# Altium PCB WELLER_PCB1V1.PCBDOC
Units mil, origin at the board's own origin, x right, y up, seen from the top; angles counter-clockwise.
Board outline 6000 x 4000 mil, 2 copper layers (Top Layer, Bottom Layer); 44 components, 40 nets, 155 pads, 1 vias.
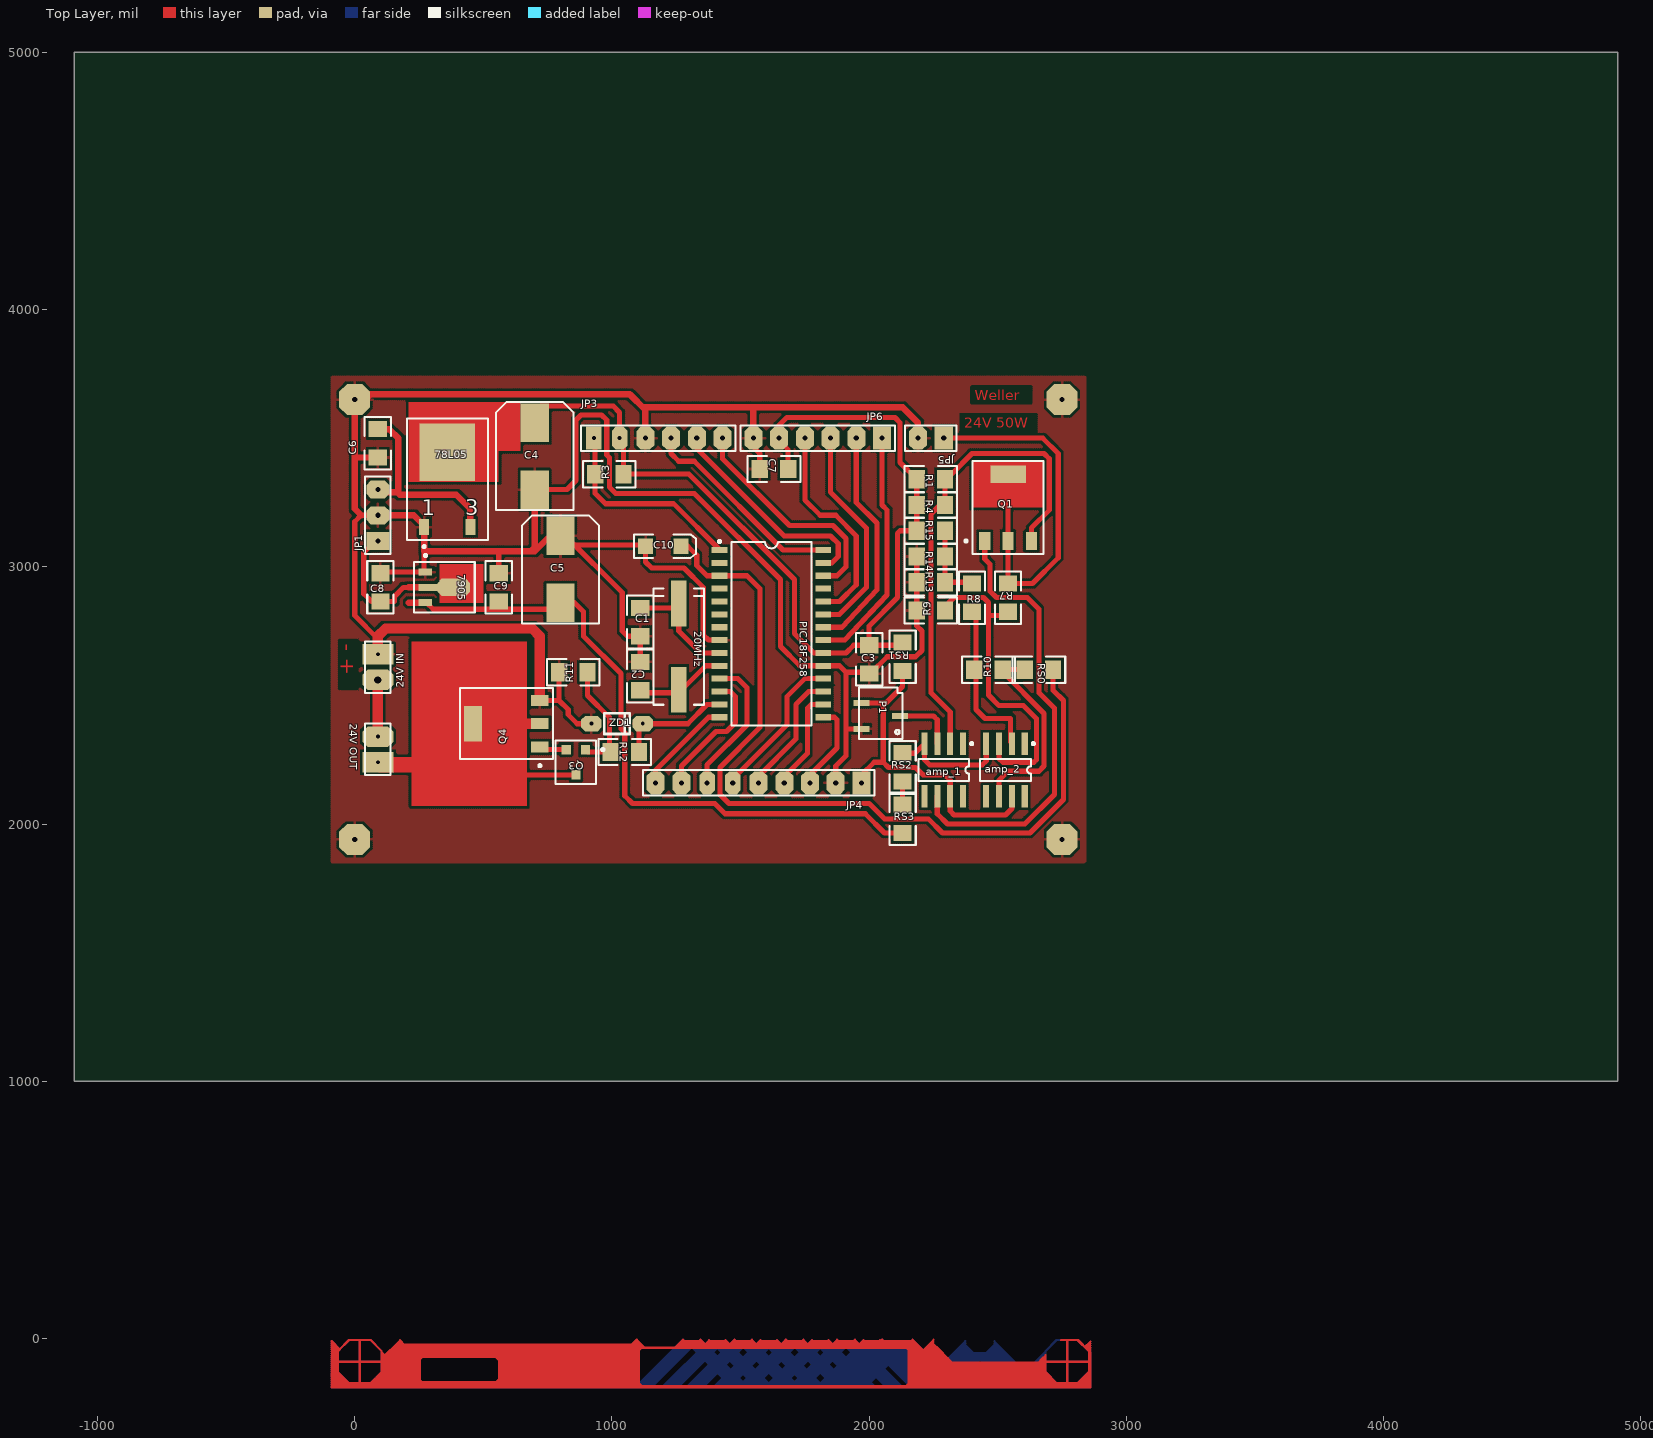
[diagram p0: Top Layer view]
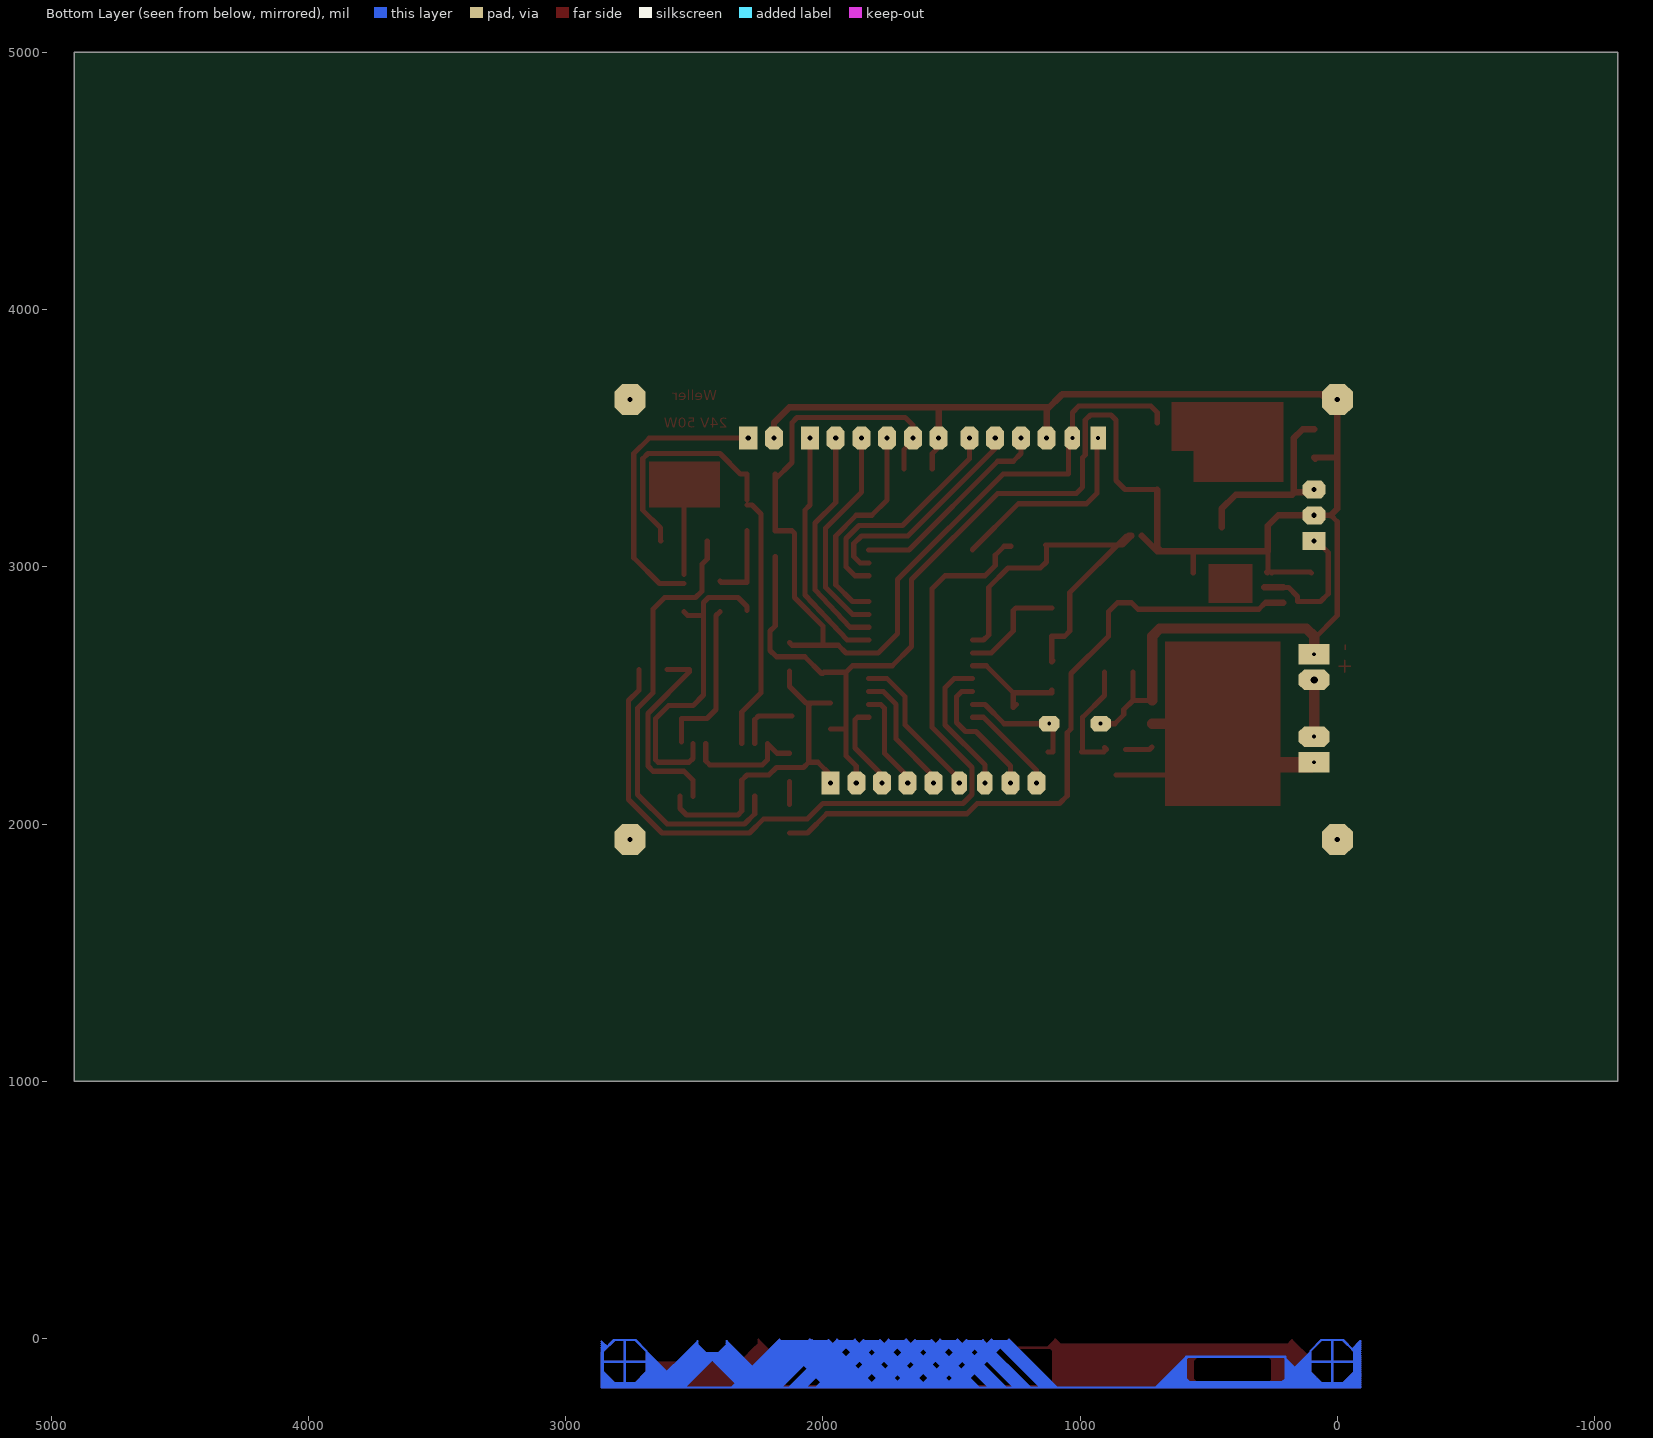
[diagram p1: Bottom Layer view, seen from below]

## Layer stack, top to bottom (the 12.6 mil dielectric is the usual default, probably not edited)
Top Layer: signal copper 1.4
Dielectric: dielectric 12.6, FR-4, Dk 4.8
Bottom Layer: signal copper 1.4

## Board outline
-1090,1000 -1090,5000 4910,5000 4910,1000

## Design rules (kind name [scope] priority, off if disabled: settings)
Clearance [All] p1: gap=10
ComponentClearance [All] p1 off: gap=10 collisioncheckmode=0
FanoutControl Fanout_BGA [IsBGA] p1 off: bgadir=Out bgaviamode=Centered fanoutstyle=Auto fanoutdirection=Alternating viagrid=1 // Fanout_BGA (Default Rule)
FanoutControl Fanout_LCC [IsLCC] p2 off: bgadir=Out bgaviamode=Centered fanoutstyle=Auto fanoutdirection=Alternating viagrid=1 // Fanout_LCC (Default Rule)
FanoutControl Fanout_SOIC [IsSOIC] p3 off: bgadir=Out bgaviamode=Centered fanoutstyle=Auto fanoutdirection=Alternating viagrid=1 // Fanout_SOIC (Default Rule)
FanoutControl Fanout_Small [(CompPinCount < 5)] p4 off: bgadir=Out bgaviamode=Centered fanoutstyle=Auto fanoutdirection=OutThenIn viagrid=1 // Fanout_Small (Default Rule)
FanoutControl Fanout_Default [All] p5 off: bgadir=Out bgaviamode=Centered fanoutstyle=Auto fanoutdirection=Alternating viagrid=1 // Fanout_Default (Default Rule)
Height [All] p1 off: minheight=0 maxheight=1000 prefheight=500
HoleSize [All] p1 off: absolutevalues=TRUE maxlimit=100 minlimit=1 maxpercent=80.000 minpercent=20.000
LayerPairs [All] p1 off: enforce=TRUE
PasteMaskExpansion [All] p1 off: expansion=0
PolygonConnect [All] p1: connectstyle=Relief reliefconductorwidth=10 reliefentries=4 polygonreliefangle="90 Angle"
RoutingCorners [All] p1 off: cornerstyle=45-Degree minsetback=100 maxsetback=100
RoutingLayers [All] p1 off: top layer=Horizontal bottom layer=Vertical
RoutingPriority [All] p1 off: routingpriority=0
RoutingTopology [All] p1 off: topology=Shortest
RoutingVias [All] p1: holewidth=28 width=50 viastyle="Through Hole" minholewidth=28 minwidth=50 maxholewidth=28 maxwidth=50
SolderMaskExpansion [All] p1 off: expansion=4
TestPointUsage [All] p1 off: valid=0 allowmultiple=FALSE
Testpoint [All] p1 off: side=15 testpointundercomponent=TRUE minsize=40 maxsize=100 preferedsize=60 minholesize=0 maxholesize=40 preferedholesize=32 testpointgrid=1 style=1023 order=1234567890
Width [All] p1: maxlimit=70 minlimit=10 preferedwidth=40 toplayer_prefwidth=20 bottomlayer_prefwidth=60 minimp=50.000000 maximp=50.000000 favimp=50.000000
4 further rules are at their usual default settings.

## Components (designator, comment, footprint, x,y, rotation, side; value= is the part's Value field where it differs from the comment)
20MHz "ECS-110-S-5P" BCY-F2/Z13 1260,2690 r270 top
"24V IN" "Header 2" HDR1X2#1 90,2660 r270 top
"24V OUT" "Header 2" HDR1X2#1 90,2240 r90 top
78L05 "MC33269DT-5.0" SIP-G3/Z11.05 360,3300 r0 top
7905 "79L05" SOT89/P1.5 330,2920 r270 top
amp_1 "TL071CD" SO-G8 2290,2210 r180 top
amp_2 "TL071CD" SO-G8 2530,2210 r180 top
C1 "Cap Semi" C3216-1206 1110,2785.12 r90 top
C2 "Cap Semi" C3216-1206 1110,2575.12 r270 top
C3 "Cap Semi" C3216-1206 2000,2640 r90 top
C4 "Cap Pol3" DSO-C3/X3.4 270,3880 r0 top
C5 "Cap Semi" DSO-C3/X3.4 370,3440 r0 top
C6 "Cap Semi" C3216-1206 90,3480 r90 top
C7 "Cap Semi" C3216-1206 1630,3380 r0 top (schematic designator C6)
C8 "Cap Semi" C3216-1206 100,2920 r90 top (schematic designator C7)
C9 "Cap Semi" C3216-1206 560,2920 r90 top (schematic designator C8)
C10 "Cap Pol3" DSO-F2/D6.1 1200,3080 r0 top
JP1 "Header 3" HDR1X3 90,3100 r90 top
JP3 "Header 6" HDR1X6#1 930,3500 r0 top
JP4 "Header 9" HDR1X9 1970,2160 r180 top
JP5 "Header 2" HDR1X2#2 2290,3500 r180 top
JP6 "Header 6" HDR1X6#2 2050,3500 r180 top
P1 "SMD POTI" "SMD poti" 2030,2420 r270 top
PIC18F258 "" SOIC28 1610,2740 r270 top
Q1 "BCP53T1" DSO-G3/C6.6 2540,3230 r0 top
Q3 "BC817" SOT23 860,2240 r180 top
Q4 "BCP56T1" DSO-G3/C6.6 590,2390 r90 top (schematic designator BDP949)
R1 "Res2" C3216-1206 2240,3340 r180 top
R3 "Res2" C3216-1206 990,3360 r0 top
R4 "Res2" C3216-1206 2240,3240 r180 top
R7 "Res2" C3216-1206 2540,2880 r270 top
R8 "Res2" C3216-1206 2400,2880 r270 top
R9 "Res2" C3216-1206 2240,2830 r0 top
R10 "Res2" C3216-1206 2463.88,2600 r0 top
R11 "Res2" C3216-1206 850,2590 r0 top
R12 "Res2" C3216-1206 1050,2280 r180 top
R13 "Res2" C3216-1206 2240,2940 r0 top
R14 "Res2" C3216-1206 2240,3040 r0 top
R15 "Res2" C3216-1206 2240,3140 r180 top
RS0 "Res2" C3216-1206 2660,2600 r0 top
RS1 "Res2" C3216-1206 2130,2650 r270 top
RS2 "Res2" C3216-1206 2130,2220 r270 top
RS3 "Res2" C3216-1206 2130,2020 r270 top
ZD1 "ZENER" Dioda200 920,2390 r0 top

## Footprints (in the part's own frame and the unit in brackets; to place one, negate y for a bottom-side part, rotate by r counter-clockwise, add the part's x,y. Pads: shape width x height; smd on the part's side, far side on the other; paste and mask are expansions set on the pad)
BCY-F2/Z13 [mm]
  rect 4.5x1.5 smd: 1(-4.25,0) 2(4.25,0)
  silkscreen extent -5.75,-2.5 5.75,2.5
C3216-1206 [mm]
  rect 1.6x1.8 smd: 1(-1.4,0) 2(1.4,0)
  silkscreen extent -2.6,-1.3 2.6,1.3
Dioda200 [mil]
  oct 80x60 hole 15: 1(0,0) 2(200,0)
  silkscreen extent 50,-40 150,40
DSO-C3/X3.4 [mil]
  rect 110x150 smd: 1(430,-320) 2(430,-580)
  silkscreen extent 280,-660 580,-240
DSO-F2/D6.1 [mm]
  rect 1.5x1.5 smd: 1(-1.75,0) 2(1.75,0)
  silkscreen extent -2.9,-1.15 3.2,1.15
DSO-G3/C6.6 [mm]
  rect 1.1x1.75 smd: 1(-2.3,-3.3) 2(0,-3.3) 3(2.3,-3.3)
  rect 3.5x1.75 smd: 4(0,3.3)
  silkscreen extent -4.27,-4.6 3.5,4.6
HDR1X2#1 [mil]
  rect 80x120 hole 15: 1(0,0)
  oct 80x120 hole 15: 2(100,0)
  silkscreen extent -50,-50 150,50
HDR1X2#2 [mil]
  rect 70x90 hole 20: 1(0,0)
  oct 70x90 hole 20: 2(100,0)
  silkscreen extent -50,-50 150,50
HDR1X3 [mil]
  rect 70x90 hole 20: 1(0,0)
  oct 70x90 hole 20: 2(100,0) 3(200,0)
  silkscreen extent -50,-50 250,50
HDR1X6#1 [mil]
  rect 60x90 hole 15: 1(0,0)
  oct 60x90 hole 15: 2(100,0)
  oct 70x90 hole 20: 3(200,0) 4(300,0) 5(400,0) 6(500,0)
  silkscreen extent -50,-50 550,50
HDR1X6#2 [mil]
  rect 70x90 hole 20: 1(0,0)
  oct 70x90 hole 20: 2(100,0) 3(200,0) 4(300,0) 5(400,0) 6(500,0)
  silkscreen extent -50,-50 550,50
HDR1X9 [mil]
  rect 70x90 hole 20: 1(0,0)
  oct 70x90 hole 20: 2(100,0) 3(200,0) 4(300,0) 5(400,0) 8(700,0) 9(800,0)
  oct 60x90 hole 20: 6(500,0) 7(600,0)
  silkscreen extent -50,-50 850,50
SIP-G3/Z11.05 [mm]
  rect 1x1.6 smd: 1(-2.285,-3.7) 3(2.285,-3.7)
  rect 5.5x5.7 smd: 4(0,3.7)
  silkscreen extent -4,-5.75 4,7.03
"SMD poti" [mm]
  rect 0.6x1.55 smd: 1(-1.27,-1.524) 2(0,2.286) 3(1.27,-1.524)
  silkscreen extent -2.79,-1.78 2.29,2.54
SO-G8 [mm]
  rect 0.6x2.2 smd: 1(-1.905,-2.6) 2(-0.635,-2.6) 3(0.635,-2.6) 4(1.905,-2.6) 5(1.905,2.6) 6(0.635,2.6) 7(-0.635,2.6) 8(-1.905,2.6)
  silkscreen extent -2.88,-2.72 2.5,1.1
SOIC28 [mm]
  rect 0.6x1.55 smd: 1(-8.255,-4.871) 2(-6.985,-4.871) 3(-5.715,-4.871) 4(-4.445,-4.871) 5(-3.175,-4.871) 6(-1.905,-4.871) 7(-0.635,-4.871) 8(0.635,-4.871) 9(1.905,-4.871) 10(3.175,-4.871) 11(4.445,-4.871) 12(5.715,-4.871) 13(6.985,-4.871) 14(8.255,-4.871) 15(8.255,5.379) 16(6.985,5.379) 17(5.715,5.379) 18(4.445,5.379) 19(3.175,5.379) 20(1.905,5.379) 21(0.635,5.379) 22(-0.635,5.379) 23(-1.905,5.379) 24(-3.175,5.379) 25(-4.445,5.379) 26(-5.715,5.379) 27(-6.985,5.379) 28(-8.255,5.379)
  silkscreen extent -9.23,-5 9.05,4.2
SOT23 [mm]
  rect 0.9x0.95 smd: B(-0.95,-1.25) C(0,1.25) E(0.95,-1.25)
  silkscreen extent -2.78,-2.15 2,2.15
SOT89/P1.5 [mm]
  oct 1.75x3.25 smd: 0(0,1.4)
  rect 0.7x1.35 smd: 1(-1.5,-1.4) 3(1.5,-1.4)
  rect 0.7x1.85 smd: 2(0,-1.15)
  silkscreen extent -3.27,-2.52 2.5,3.47

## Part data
20MHz: "Crystal Oscillator"
"24V IN" "24V OUT" JP5: "Header, 2-Pin"
78L05: "Low Dropout Positive Fixed Voltage Regulator"
amp_1 amp_2: "Low-Noise J-FET Single Operational Amplifier"
C1 C2 C3 C5 C6 C7 C8 C9: "Capacitor (Semiconductor SIM Model)"
C4 C10: "Polarized Capacitor (Surface Mount)"
JP1: "Header, 3-Pin"
JP3 JP6: "Header, 6-Pin"
JP4: "Header, 9-Pin"
P1: library part RPot1, "Potentiometer"
PIC18F258: library part PIC18F258
Q1: "PNP Silicon Epitaxial Transistor"
Q4: "NPN Silicon Epitaxial Transistor"
R1 R3 R4 R7 R8 R9 R10 R11 R12 R13 R14 R15 RS0 RS1 RS2 RS3: "Resistor"

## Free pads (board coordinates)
  oct 120x120 hole 20: 3(0,3650) 4(2750,3650) 5(0,1940) 6(2750,1940)

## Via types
v1: diameter 50, hole 28, Top Layer to Bottom Layer, 1 vias

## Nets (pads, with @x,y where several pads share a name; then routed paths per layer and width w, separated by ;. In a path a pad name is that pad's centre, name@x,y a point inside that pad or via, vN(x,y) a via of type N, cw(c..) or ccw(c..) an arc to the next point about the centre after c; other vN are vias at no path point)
GND: 78L05.1 7905.1 "24V IN.1" C1.1 C2.1 C3.1 C4.2 C5.1 C6.1 C7.1 C8.2 C9.2 C10.1 JP1.2 JP3.3 JP4.2 JP5.2 JP6.6 P1.3 pad.3 pad.4 pad.5 pad.6 PIC18F258.8 PIC18F258.19 Q4.3 R9.1 R11.1 R13.1 R14.1 ZD1.1 | length 11588.4
  Top Layer w20: 90,2720 0,2810 0,3175 25,3200 JP1.2 ; C8.2 103.94,2979.05 7905.1 ; 7905.1@255.12,2975.12 7905.1@259.05,2979.05 ; 270,3060 270,2983.94 7905.1 ; 7905.1@270.95,2975.12 7905.1 ; C9.2 560,3060 ; C4.2 825,3300 860,3335 860,3570 880,3590 960,3590 980,3570 980,3435 990,3425 990,3310 1015,3285 1320,3285 1655,2950 1655,2690 1730,2615 1885,2615 1910,2590 ; Q4.3 794.45,2480.55 ; R11.1 794.88,2480.98 794.45,2480.55 ; ZD1.1 865,2390 830,2425 830,2445 794.45,2480.55 ; C2.1@1105.12,2635.12 C2.1 C1.1 1060,2730 1040,2750 1040,2900 820,3120 C5.1 835,3085 C10.1@1135,3085 ; JP3.3 JP3.3@1130,3540 ; C10.1 1131.1,3018.9 1155,2995 1280,2995 1355,2920 1355,2735 1375,2715 PIC18F258.8 ; JP6.6 1550,3465 1574.88,3440.12 C7.1 ; JP4.2 1870,2225 1910,2265 1910,2590 ; 1910,2370 P1.3 ; R14.1 2184.88,2770.12 2205,2750 2205,2675 2180,2650 2070,2650 2004.88,2584.88 C3.1 1994.88,2590 1910,2590
  Top Layer w25: 0.12,3424.88 C6.1 C6.1@85.12,3420 ; 25,3200 0,3225 0,3610 60,3670 1070,3670 1130,3610 JP3.3 ; JP1.2 230,3200 78L05.1@270.01,3159.99 ; 78L05.1 270.01,3060.01 700,3060 C5.1@760,3120 ; 685,3060 700,3075 C4.2 ; C5.1 C5.1@810,3120 ; 1120,3620 2130,3620 2190,3560 JP5.2 ; JP6.6 1550,3620
  Top Layer w40: 90,2660 90,2730 120,2760 690,2760 719.92,2730.08 Q4.3
Net20MHz_1: 20MHz.1 C1.2 PIC18F258.9 | length 427.7
  Top Layer w20: C1.2 1249.76,2840.24 1260,2830 1260,2750 1345,2665 PIC18F258.9
Net20MHz_2: 20MHz.2 C2.2 PIC18F258.10 | length 436.3
  Top Layer w20: C2.2 1110,2510 20MHz.2@1260,2510 ; 20MHz.2@1247.8,2464.88 1260,2452.68 20MHz.2@1260,2510 ; PIC18F258.10 1365,2615 20MHz.2@1260,2510
"Net24V IN_2": "24V IN.2" "24V OUT.2" | length 220
  Top Layer w40: 90,2340 v1(90,2560)
"Net24V OUT_1": "24V OUT.1" Q3.C Q4.2 Q4.4 | length 865.2
  Top Layer w20: 635,2190 635.79,2190.79 Q3.C
  Top Layer w40: Q4.4 Q4.2
  Top Layer w60: 100,2230 480,2230
Net78L05_3: 78L05.3 C6.2 JP1.3 | length 771.3
  Top Layer w25: JP1.3 100,3290 170,3290 170,3500 134.88,3535.12 C6.2 ; 165,3290 175,3280 395,3280 449.96,3225.04 78L05.3
Net7905_2: 7905.0 7905.2 C8.1 JP1.1 | length 530.5
  Top Layer w20: JP1.1 80,3100 35,3055 35,2894.88 65,2864.88 154.88,2864.88 154.88,2884.88 190,2920 210,2920
  Top Layer w25: 210,2920 7905.2
NetC10_2: C10.2 PIC18F258.3 RS0.2 | length 3234.7
  Top Layer w20: C10.2 1295,3080 1330,3045 1330,3005 1370,2965 1525,2965 1575,2915 1575,2375 1420,2220 1420,2115 1455,2080 2000,2080 2060,2020 2230,2020 2285,1965 2625,1965 2755,2095 2755,2480 2715.12,2519.88 RS0.2 ; PIC18F258.3@1418.11,2965.12 PIC18F258.3
NetJP3_1: JP3.1 PIC18F258.1 R3.1 | length 792.5
  Top Layer w20: JP3.1 934.88,3495.12 934.88,3285 974.88,3245 1240,3245 1418.23,3066.77 PIC18F258.1
NetJP3_4: JP3.4 PIC18F258.28 | length 807.1
  Top Layer w20: JP3.4 1230,3440 1260,3410 1320,3410 1665,3065 PIC18F258.28
NetJP3_5: JP3.5 PIC18F258.27 | length 861.8
  Top Layer w20: JP3.5 1330,3460 1670,3120 1850,3120 1880,3090 1880,3040 1855,3015 PIC18F258.27
NetJP3_6: JP3.6 PIC18F258.26 | length 901.1
  Top Layer w20: JP3.6 1430,3420 1690,3160 1860,3160 1910,3110 1910,3000 1875,2965 PIC18F258.26
NetJP4_1: amp_1.7 amp_2.7 JP4.1 P1.1 RS1.2 | length 1329.9
  Top Layer w20: JP4.1 1970,2190 2020,2240 2055,2240 ; P1.1 2065,2470 2130,2535 RS1.2 ; 2045,2470 2055,2460 2055,2240 ; amp_2.7 2555,2060 2530,2035 2330,2035 2315,2050 2315,2170 2295,2190 2210,2190 2180,2220 2075,2220 2055,2240
NetJP4_3: JP4.3 PIC18F258.15 | length 345.9
  Top Layer w20: JP4.3 1770,2190 1875,2295 1875,2405 1865,2415 PIC18F258.15
NetJP4_4: JP4.4 PIC18F258.16 | length 395.3
  Top Layer w20: JP4.4 1670,2185 1760,2275 1760,2450 1775,2465 PIC18F258.16
NetJP4_5: JP4.5 PIC18F258.17 | length 492.5
  Top Layer w20: JP4.5 1570,2185 1715,2330 1715,2465 1765,2515 PIC18F258.17
NetJP4_6: JP4.6 PIC18F258.18 | length 592.8
  Top Layer w20: JP4.6 1470,2175 1680,2385 1680,2495 1750,2565 PIC18F258.18
NetJP4_7: JP4.7 PIC18F258.11 | length 555.5
  Top Layer w20: JP4.7 1370,2230 1525,2385 1525,2530 1490,2565 PIC18F258.11
NetJP4_8: JP4.8 PIC18F258.12 | length 515.5
  Top Layer w20: JP4.8 1270,2225 1405,2360 1445,2360 1480,2395 1480,2495 1460,2515 PIC18F258.12
NetJP4_9: JP4.9 PIC18F258.14 | length 383.1
  Top Layer w20: JP4.9 1170,2210 1375,2415 PIC18F258.14
NetJP5_1: JP5.1 Q1.2 Q1.4 R7.1 | length 1501.1
  Top Layer w20: JP5.1 2675,3500 2735,3440 2735,3035 2635.12,2935.12 R7.1 ; 2540,2970 Q1.4
NetJP6_1: JP6.1 PIC18F258.21 | length 942
  Top Layer w20: PIC18F258.21 1905,2715 2070,2890 2070,3220 2050,3240 JP6.1
NetJP6_2: JP6.2 PIC18F258.22 | length 894.5
  Top Layer w20: PIC18F258.22 1895,2765 2030,2910 2030,3170 1950,3250 JP6.2
NetJP6_3: JP6.3 PIC18F258.23 | length 849.7
  Top Layer w20: PIC18F258.23 1885,2815 1990,2920 1990,3150 1850,3290 JP6.3
NetJP6_4: JP6.4 PIC18F258.24 | length 843.1
  Top Layer w20: JP6.4 1750,3260 1810,3200 1870,3200 1950,3120 1950,2930 1885,2865 PIC18F258.24
NetP1_2: amp_1.3 P1.2 | length 243.9
  Top Layer w20: P1.2 2250,2420 2265,2405 amp_1.3
NetPIC18F258_5: PIC18F258.5
NetPIC18F258_13: PIC18F258.13 R12.1 ZD1.2 | length 465.4
  Top Layer w20: ZD1.2@1090,2390 1105.12,2374.88 R12.1 R12.1@1125,2280 ; ZD1.2 1295,2390 1370,2465 PIC18F258.13
NetQ1_1: amp_1.6 Q1.1 | length 1754.3
  Top Layer w20: amp_1.6 2265,2040 2305,2000 2605,2000 2720,2115 2720,2450 2660,2510 2660,2835 2615,2880 2495,2880 2470,2905 2470,3010 2449.45,3030.55 Q1.1
NetQ1_3: amp_1.2 Q1.3 R1.1 R4.1 | length 1889.1
  Top Layer w20: R4.1 2275,3240 2240,3205 2240,2510 2315,2435 amp_1.2 ; R4.1@2295.12,3260 2295.12,3360 2320,3360 2400,3440 2680,3440 2700,3420 2700,3220 2630.55,3150.55 Q1.3 Q1.3@2630,3099.53
NetQ3_B: Q3.B R11.2 R12.2 | length 446.4
  Top Layer w20: Q3.B Q3.B@905.12,2296.93 ; R11.2 905.12,2499.88 990,2415 990,2284.88 R12.2 Q3.B@906.61,2280
NetQ3_E: Q3.E Q4.1 | length 106.9
  Top Layer w20: Q4.1 730.16,2289.21 Q3.E
NetR7_2: amp_2.3 R7.2 R9.2 | length 1245
  Top Layer w20: R9.2 2295.12,2845.12 2330,2880 2445,2880 2463.88,2861.12 2463.88,2501.12 2505,2460 2600,2460 2650,2410 2650,2250 2640,2240 2520,2240 2505,2255 amp_2.3 ; 2463.88,2810 2525.12,2810 R7.2
NetR8_1: R8.1 R13.2 R14.2 R15.1 | length 307
  Top Layer w20: R15.1 R13.2 2394.88,2940 R8.1@2400,2945.12
NetR8_2: amp_2.2 R8.2 R10.1 | length 625.6
  Top Layer w20: R8.2 2414.88,2810 2414.88,2445.12 2450,2410 2550,2410 amp_2.2@2550,2320
NetR10_2: amp_2.6 R10.2 RS0.1 | length 787.7
  Top Layer w20: amp_2.6 2505,2170 2540,2205 2660,2205 2680,2225 2680,2430 2519,2591 R10.2 RS0.1
NetRS2_1: amp_1.4 amp_2.4 RS2.1 | length 484.6
  Top Layer w20: RS2.1 2177.76,2275.12 amp_1.4 2215,2250 2235,2230 2440,2230 2455,2245 amp_2.4
NetRS2_2: RS2.2 RS3.1 | length 89.8
  Top Layer w20: RS3.1 RS2.2
VCC: 7905.3 C5.2 C9.1 RS3.2 | length 2636.1
  Top Layer w20: 7905.3@279.06,2860.94 305.12,2834.88 774.88,2834.88 C5.2 854.88,2860 890,2824.88 890,2730 1035,2585 1035,2370 1050,2355 1050,2110 1080,2080 1400,2080 1440,2040 1984.88,2040 2060,1964.88 RS3.2
  Top Layer w25: 210.95,2860.95 7905.3@279.05,2860.95
VDD: 78L05.4 C3.2 C4.1 C7.2 JP3.2 JP6.5 PIC18F258.20 R1.2 R3.2 R4.2 R15.2 RS1.1 | length 3841
  Top Layer w20: C4.1 700,3600 725,3625 1005,3625 1030,3600 JP3.2 1045.12,3484.88 R3.2 1300,3360 1710,2950 1710,2740 1785,2665 PIC18F258.20 1910,2665 1940.12,2695.12 2120,2695.12 RS1.1 ; JP6.5@1650,3490 1685.12,3454.88 C7.2 ; JP6.5 1650,3550 1680,3580 2100,3580 2120,3560 2120,3404.88 R1.2 ; C3.2 2000,2770 2110,2880 2110,3130 2120,3140 R15.2 R1.2@2184.88,3360
pads on no net: amp_1.1 amp_1.5 amp_1.8 amp_2.1 amp_2.5 amp_2.8 PIC18F258.2 PIC18F258.4 PIC18F258.6 PIC18F258.7 PIC18F258.25
copper on no net: | length 160575.9
  Top Layer w8: -90,-190 2860,-190 ; -90,-66 -64,-92 ; -90,-58 -64,-84 ; -90,-50 -64,-76 ; -90,-42 -64,-68 ; -90,-34 -64,-60 ; -90,-26 -64,-52 ; -90,-18 -62,-46 ; -90,-10 -58,-42 ; -64,-128 -90,-154 -54,-190 -30,-166 ; -64,-124 -90,-98 -64,-72 ; -64,-120 -90,-146 -46,-190 -26,-170 ; -64,-116 -90,-90 -64,-64 ; -64,-112 -90,-138 -38,-190 -22,-174 ; -64,-108 -90,-82 -64,-56 ; -64,-104 -90,-130 -30,-190 -14,-174 2,-190 18,-174 34,-190 50,-174 66,-190 232,-24 ; -64,-100 -90,-74 -64,-48 ; -64,-96 -90,-122 -22,-190 -6,-174 10,-190 26,-174 42,-190 58,-174 74,-190 240,-24 ; -64,-88 -90,-114 -14,-190 2,-174 18,-190 34,-174 50,-190 216,-24 ; -64,-80 -90,-106 -64,-132 ; -62,-134 -90,-162 -62,-190 -34,-162 ; -58,-138 -90,-170 -70,-190 -38,-158 ; -54,-142 -90,-178 -78,-190 -42,-154 ; -46,-150 -86,-190 -90,-186 ; 64,-172 82,-190 248,-24 ; 68,-168 90,-190 256,-24 ; 72,-164 98,-190 264,-24 ; 76,-160 106,-190 272,-24 ; 80,-156 114,-190 280,-24 ; 84,-152 122,-190 288,-24 ; 88,-148 130,-190 296,-24 ; 92,-144 138,-190 253,-75 256.99,-71.01 304,-24 ; 96,-140 146,-190 253,-83 264.99,-71.01 312,-24 ; 100,-136 154,-190 253,-91 ; 104,-128 208,-24 ; 104,-124 170,-190 253,-107 ; 104,-120 200,-24 ; 104,-116 178,-190 253,-115 ; 104,-112 192.5,-23.5 ; 104,-108 186,-190 253,-123 ; 104,-104 188.5,-19.5 ; 104,-100 194,-190 253,-131 ; 104,-96 184.5,-15.5 ; 104,-92 202,-190 253,-139 ; 104,-88 180.5,-11.5 ; 104,-84 210,-190 253,-147 ; 104,-80 176.5,-7.5 ; 104,-76 218,-190 253,-155 ; 104,-68 226,-190 253,-163 ; 104,-60 234,-190 255,-169 ; 104,-52 242,-190 263,-169 ; 196,-24 253,-81 ; 204,-24 253,-73 ; 212,-24 259.01,-71.01 ; 220,-24 267.01,-71.01 ; 224,-24 58,-190 42,-174 26,-190 10,-174 -6,-190 -22,-174 ; 228,-24 275.01,-71.01 ; 236,-24 283.01,-71.01 ; 244,-24 291.01,-71.01 ; 250,-190 271,-169 ; 252,-24 299.01,-71.01 ; 253,-161 261,-169 282,-190 303,-169 ; 253,-99 162,-190 104,-132 ; 258,-190 279,-169 ; 260,-24 307.01,-71.01 ; 266,-190 287,-169 ; 268,-24 315.01,-71.01 ; 269,-169 290,-190 311,-169 ; 272.99,-71.01 320,-24 ; 274,-190 295,-169 ; 276,-24 323.01,-71.01 ; 277,-169 298,-190 319,-169 ; 280.99,-71.01 328,-24 ; 284,-24 331.01,-71.01 ; 285,-169 306,-190 327,-169 ; 288.99,-71.01 336,-24 ; 292,-24 339.01,-71.01 ; 293,-169 314,-190 335,-169 ; 296.99,-71.01 344,-24 ; 300,-24 347.01,-71.01 ; 301,-169 322,-190 343,-169 ; 304.99,-71.01 352,-24 ; 308,-24 355.01,-71.01 ; 309,-169 330,-190 351,-169 ; 312.99,-71.01 360,-24 ; 316,-24 363.01,-71.01 ; 317,-169 338,-190 359,-169 ; 320.99,-71.01 368,-24 ; 324,-24 371.01,-71.01 ; 325,-169 346,-190 367,-169 ; 328.99,-71.01 376,-24 ; 332,-24 379.01,-71.01 ; 333,-169 354,-190 375,-169 ; 336.99,-71.01 384,-24 ; 340,-24 387.01,-71.01 ; 341,-169 362,-190 383,-169 ; 344.99,-71.01 392,-24 ; 348,-24 395.01,-71.01 ; 349,-169 370,-190 391,-169 ; 352.99,-71.01 400,-24 ; 356,-24 403.01,-71.01 ; 357,-169 378,-190 399,-169 ; 360.99,-71.01 408,-24 ; 364,-24 411.01,-71.01 ; 365,-169 386,-190 407,-169 ; 368.99,-71.01 416,-24 ; 372,-24 419.01,-71.01 ; 373,-169 394,-190 415,-169 ; 376.99,-71.01 424,-24 ; 380,-24 427.01,-71.01 ; 381,-169 402,-190 423,-169 ; 384.99,-71.01 432,-24 ; 388,-24 435.01,-71.01 ; 389,-169 410,-190 431,-169 ; 392.99,-71.01 440,-24 ; 396,-24 443.01,-71.01 ; 397,-169 418,-190 439,-169 ; 400.99,-71.01 448,-24 ; 404,-24 451.01,-71.01 ; 405,-169 426,-190 447,-169 ; 408.99,-71.01 456,-24 ; 412,-24 459.01,-71.01 ; 413,-169 434,-190 455,-169 ; 416.99,-71.01 464,-24 ; 420,-24 467.01,-71.01 ; 421,-169 442,-190 463,-169 ; 424.99,-71.01 472,-24 ; 428,-24 475.01,-71.01 ; 429,-169 450,-190 471,-169 ; 432.99,-71.01 480,-24 ; 436,-24 483.01,-71.01 ; 437,-169 458,-190 479,-169 ; 440.99,-71.01 488,-24 ; 444,-24 491.01,-71.01 ; 445,-169 466,-190 487,-169 ; 448.99,-71.01 496,-24 ; 452,-24 499.01,-71.01 ; 453,-169 474,-190 495,-169 ; 456.99,-71.01 504,-24 ; 460,-24 507.01,-71.01 ; 461,-169 482,-190 503,-169 ; 464.99,-71.01 512,-24 ; 468,-24 515.01,-71.01 ; 469,-169 490,-190 511,-169 ; 472.99,-71.01 520,-24 ; 476,-24 523.01,-71.01 ; 477,-169 498,-190 519,-169 ; 480.99,-71.01 528,-24 ; 484,-24 531.01,-71.01 ; 485,-169 506,-190 527,-169 ; 488.99,-71.01 536,-24 ; 492,-24 539.01,-71.01 ; 493,-169 514,-190 535,-169 ; 496.99,-71.01 544,-24 ; 500,-24 547.01,-71.01 560.92,-84.92 666,-190 832,-24 ; 501,-169 522,-190 543,-169 ; 504.99,-71.01 552,-24 ; 508,-24 555.01,-71.01 560.92,-76.92 674,-190 840,-24 ; 509,-169 530,-190 551,-169 560.92,-159.08 696,-24 ; 512.99,-71.01 560,-24 ; 516,-24 682,-190 848,-24 ; 517,-169 538,-190 559,-169 560.92,-167.08 704,-24 ; 520.99,-71.01 568,-24 ; 524,-24 690,-190 856,-24 ; 525,-169 546,-190 712,-24 ; 528.99,-71.01 576,-24 ; 532,-24 698,-190 864,-24 ; 533,-169 554,-190 720,-24 ; 536.99,-71.01 584,-24 ; 540,-24 706,-190 872,-24 ; 541,-169 562,-190 728,-24 ; 544.99,-71.01 592,-24 ; 548,-24 714,-190 880,-24 ; 549,-169 570,-190 736,-24 ; 552.99,-71.01 600,-24 ; 556,-24 722,-190 888,-24 ; 557,-169 578,-190 744,-24 ; 560.92,-164.92 586,-190 752,-24 ; 560.92,-156.92 594,-190 760,-24 ; 560.92,-151.08 688,-24 ; 560.92,-148.92 602,-190 768,-24 ; 560.92,-143.08 680,-24 ; 560.92,-140.92 610,-190 776,-24 ; 560.92,-135.08 672,-24 ; 560.92,-132.92 618,-190 784,-24 ; 560.92,-127.08 664,-24 ; 560.92,-124.92 626,-190 792,-24 ; 560.92,-119.08 656,-24 ; 560.92,-116.92 634,-190 800,-24 ; 560.92,-111.08 648,-24 ; 560.92,-108.92 642,-190 808,-24 ; 560.92,-103.08 640,-24 ; 560.92,-100.92 650,-190 816,-24 ; 560.92,-95.08 632,-24 ; 560.92,-92.92 658,-190 824,-24 ; 560.92,-87.08 624,-24 ; 560.92,-79.08 616,-24 ; 560.92,-71.08 608,-24 ; 564,-24 730,-190 896,-24 ; 572,-24 738,-190 904,-24 ; 580,-24 746,-190 912,-24 ; 588,-24 754,-190 920,-24 ; 596,-24 762,-190 928,-24 ; 604,-24 770,-190 936,-24 ; 612,-24 778,-190 944,-24 ; 620,-24 786,-190 952,-24 ; 628,-24 794,-190 960,-24 ; 636,-24 802,-190 968,-24 ; 644,-24 810,-190 976,-24 ; 652,-24 818,-190 984,-24 ; 660,-24 826,-190 992,-24 ; 668,-24 834,-190 1000,-24 ; 676,-24 842,-190 1008,-24 ; 684,-24 850,-190 1016,-24 ; 692,-24 858,-190 1024,-24 ; 700,-24 866,-190 1032,-24 ; 708,-24 874,-190 1040,-24 ; 716,-24 882,-190 1048,-24 ; 724,-24 890,-190 1056,-24 ; 732,-24 898,-190 1064,-24 ; 740,-24 906,-190 1072,-24 ; 748,-24 914,-190 ; 756,-24 922,-190 ; 764,-24 930,-190 ; 772,-24 938,-190 ; 780,-24 946,-190 ; 788,-24 954,-190 1106,-38 ; 796,-24 962,-190 1106,-46 ; 804,-24 970,-190 1106,-54 1076,-24 ; 812,-24 978,-190 1106,-62 1068,-24 ; 820,-24 986,-190 1106,-70 1060,-24 ; 828,-24 994,-190 1106,-78 1052,-24 ; 836,-24 1002,-190 1106,-86 1044,-24 ; 844,-24 1010,-190 1106,-94 1036,-24 ; 852,-24 1018,-190 1106,-102 1028,-24 ; 860,-24 1026,-190 1106,-110 1020,-24 ; 868,-24 1034,-190 1106,-118 1012,-24 ; 876,-24 1042,-190 1106,-126 1004,-24 ; 884,-24 1050,-190 1106,-134 996,-24 ; 892,-24 1058,-190 1106,-142 988,-24 ; 900,-24 1066,-190 1106,-150 980,-24 ; 908,-24 1074,-190 1106,-158 972,-24 ; 916,-24 1082,-190 1106,-166 964,-24 ; 924,-24 1090,-190 1106,-174 ; 932,-24 1098,-190 1106,-182 ; 940,-24 1106,-190 1112.01,-183.99 ; 948,-24 1106,-182 ; 956,-24 1106,-174 ; 1080.5,-20.5 1106,-46 ; 1084.5,-16.5 1106,-38 ; 1088.5,-12.5 1112.02,-36.02 ; 1092.5,-8.5 1120.02,-36.02 ; 1096.5,-4.5 1128.02,-36.02 ; 1107.98,-36.02 1106,-38 ; 1115.98,-36.02 1106,-46 ; 1120.01,-183.99 1114,-190 1107.99,-183.99 1106,-182 ; 1123.99,-183.99 1130,-190 1136.01,-183.99 ; 1128.01,-183.99 1122,-190 1115.99,-183.99 1106,-174 ; 1131.99,-183.99 1138,-190 1144.01,-183.99 ; 1139.99,-183.99 1146,-190 1152.01,-183.99 ; 1147.99,-183.99 1154,-190 1160.01,-183.99 ; 1155.99,-183.99 1162,-190 1168.01,-183.99 ; 1163.99,-183.99 1170,-190 1176.01,-183.99 ; 1171.99,-183.99 1178,-190 1184.01,-183.99 ; 1179.99,-183.99 1186,-190 1192.01,-183.99 ; 1187.99,-183.99 1194,-190 1200.01,-183.99 ; 1195.99,-183.99 1202,-190 1208.01,-183.99 ; 1203.99,-183.99 1210,-190 1216.01,-183.99 ; 1211.99,-183.99 1218,-190 1224.01,-183.99 ; 1219.99,-183.99 1226,-190 1232.01,-183.99 ; 1227.99,-183.99 1234,-190 1240.01,-183.99 ; 1235.99,-183.99 1242,-190 1248.01,-183.99 ; 1243.99,-183.99 1250,-190 1256.01,-183.99 ; 1243.98,-36.02 1275.75,-4.25 ; 1251.99,-183.99 1258,-190 1264.01,-183.99 ; 1251.98,-36.02 1279.75,-8.25 ; 1259.99,-183.99 1266,-190 1272.01,-183.99 ; 1259.98,-36.02 1287,-9 ; 1267.99,-183.99 1274,-190 1280.01,-183.99 ; 1267.98,-36.02 1295,-9 ; 1275.99,-183.99 1282,-190 1288.01,-183.99 ; 1275.98,-36.02 1303,-9 ; 1280.5,-9 1339.5,-9 ; 1283.99,-183.99 1290,-190 1296.01,-183.99 ; 1283.98,-36.02 1311,-9 ; 1285,-9 1312.02,-36.02 ; 1291.99,-183.99 1298,-190 1304.01,-183.99 ; 1291.98,-36.02 1319,-9 ; 1293,-9 1320.02,-36.02 ; 1299.99,-183.99 1306,-190 1312.01,-183.99 ; 1299.98,-36.02 1327,-9 ; 1301,-9 1328.02,-36.02 ; 1307.99,-183.99 1314,-190 1320.01,-183.99 ; 1307.98,-36.02 1335,-9 ; 1309,-9 1336.02,-36.02 ; 1315.99,-183.99 1322,-190 1328.01,-183.99 ; 1317,-9 1344.02,-36.02 ; 1323.99,-183.99 1330,-190 1336.01,-183.99 ; 1325,-9 1352.02,-36.02 ; 1331.99,-183.99 1338,-190 1344.01,-183.99 ; 1333,-9 1360.02,-36.02 ; 1339.99,-183.99 1346,-190 1352.01,-183.99 ; 1340.25,-8.25 1368.02,-36.02 ; 1344.25,-4.25 1376.02,-36.02 ; 1347.99,-183.99 1354,-190 1360.01,-183.99 ; 1347.98,-36.02 1377.75,-6.25 ; 1355.99,-183.99 1362,-190 1368.01,-183.99 ; 1355.98,-36.02 1383,-9 ; 1363.99,-183.99 1370,-190 1376.01,-183.99 ; 1363.98,-36.02 1391,-9 ; 1371.99,-183.99 1378,-190 1384.01,-183.99 ; 1371.98,-36.02 1399,-9 ; 1379.99,-183.99 1386,-190 1392.01,-183.99 ; 1379.98,-36.02 1407,-9 ; 1380.5,-9 1439.5,-9 ; 1381,-9 1408.02,-36.02 ; 1387.99,-183.99 1394,-190 1400.01,-183.99 ; 1387.98,-36.02 1415,-9 ; 1389,-9 1416.02,-36.02 ; 1395.99,-183.99 1402,-190 1408.01,-183.99 ; 1395.98,-36.02 1423,-9 ; 1397,-9 1424.02,-36.02 ; 1403.99,-183.99 1410,-190 1416.01,-183.99 ; 1403.98,-36.02 1431,-9 ; 1405,-9 1432.02,-36.02 ; 1411.99,-183.99 1418,-190 1424.01,-183.99 ; 1411.98,-36.02 1439,-9 ; 1413,-9 1440.02,-36.02 ; 1419.99,-183.99 1426,-190 1432.01,-183.99 ; 1421,-9 1448.02,-36.02 ; 1427.99,-183.99 1434,-190 1440.01,-183.99 ; 1429,-9 1456.02,-36.02 ; 1435.99,-183.99 1442,-190 1448.01,-183.99 ; 1437,-9 1464.02,-36.02 ; 1442.25,-6.25 1472.02,-36.02 ; 1443.99,-183.99 1450,-190 1456.01,-183.99 ; 1443.98,-36.02 1475.75,-4.25 ; 1451.99,-183.99 1458,-190 1464.01,-183.99 ; 1451.98,-36.02 1479.75,-8.25 ; 1459.99,-183.99 1466,-190 1472.01,-183.99 ; 1459.98,-36.02 1487,-9 ; 1467.99,-183.99 1474,-190 1480.01,-183.99 ; 1467.98,-36.02 1495,-9 ; 1475.99,-183.99 1482,-190 1488.01,-183.99 ; 1475.98,-36.02 1503,-9 ; 1480.5,-9 1539.5,-9 ; 1483.99,-183.99 1490,-190 1496.01,-183.99 ; 1483.98,-36.02 1511,-9 ; 1485,-9 1512.02,-36.02 ; 1491.99,-183.99 1498,-190 1504.01,-183.99 ; 1491.98,-36.02 1519,-9 ; 1493,-9 1520.02,-36.02 ; 1499.99,-183.99 1506,-190 1512.01,-183.99 ; 1499.98,-36.02 1527,-9 ; 1501,-9 1528.02,-36.02 ; 1507.99,-183.99 1514,-190 1520.01,-183.99 ; 1507.98,-36.02 1535,-9 ; 1509,-9 1536.02,-36.02 ; 1515.99,-183.99 1522,-190 1528.01,-183.99 ; 1517,-9 1544.02,-36.02 ; 1523.99,-183.99 1530,-190 1536.01,-183.99 ; 1525,-9 1552.02,-36.02 ; 1531.99,-183.99 1538,-190 1544.01,-183.99 ; 1533,-9 1560.02,-36.02 ; 1539.99,-183.99 1546,-190 1552.01,-183.99 ; 1540.25,-8.25 1568.02,-36.02 ; 1544.25,-4.25 1576.02,-36.02 ; 1547.99,-183.99 1554,-190 1560.01,-183.99 ; 1547.98,-36.02 1577.75,-6.25 ; 1555.99,-183.99 1562,-190 1568.01,-183.99 ; 1555.98,-36.02 1583,-9 ; 1563.99,-183.99 1570,-190 1576.01,-183.99 ; 1563.98,-36.02 1591,-9 ; 1571.99,-183.99 1578,-190 1584.01,-183.99 ; 1571.98,-36.02 1599,-9 ; 1579.99,-183.99 1586,-190 1592.01,-183.99 ; 1579.98,-36.02 1607,-9 ; 1580.5,-9 1639.5,-9 ; 1581,-9 1608.02,-36.02 ; 1587.99,-183.99 1594,-190 1600.01,-183.99 ; 1587.98,-36.02 1615,-9 ; 1589,-9 1616.02,-36.02 ; 1595.99,-183.99 1602,-190 1608.01,-183.99 ; 1595.98,-36.02 1623,-9 ; 1597,-9 1624.02,-36.02 ; 1603.99,-183.99 1610,-190 1616.01,-183.99 ; 1603.98,-36.02 1631,-9 ; 1605,-9 1632.02,-36.02 ; 1611.99,-183.99 1618,-190 1624.01,-183.99 ; 1611.98,-36.02 1639,-9 ; 1613,-9 1640.02,-36.02 ; 1619.99,-183.99 1626,-190 1632.01,-183.99 ; 1621,-9 1648.02,-36.02 ; 1627.99,-183.99 1634,-190 1640.01,-183.99 ; 1629,-9 1656.02,-36.02 ; 1635.99,-183.99 1642,-190 1648.01,-183.99 ; 1637,-9 1664.02,-36.02 ; 1642.25,-6.25 1672.02,-36.02 ; 1643.99,-183.99 1650,-190 1656.01,-183.99 ; 1643.98,-36.02 1675.75,-4.25 ; 1651.99,-183.99 1658,-190 1664.01,-183.99 ; 1651.98,-36.02 1679.75,-8.25 ; 1659.99,-183.99 1666,-190 1672.01,-183.99 ; 1659.98,-36.02 1687,-9 ; 1667.99,-183.99 1674,-190 1680.01,-183.99 ; 1667.98,-36.02 1695,-9 ; 1675.99,-183.99 1682,-190 1688.01,-183.99 ; 1675.98,-36.02 1703,-9 ; 1680.5,-9 1739.5,-9 ; 1683.99,-183.99 1690,-190 1696.01,-183.99 ; 1683.98,-36.02 1711,-9 ; 1685,-9 1712.02,-36.02 ; 1691.99,-183.99 1698,-190 1704.01,-183.99 ; 1691.98,-36.02 1719,-9 ; 1693,-9 1720.02,-36.02 ; 1699.99,-183.99 1706,-190 1712.01,-183.99 ; 1699.98,-36.02 1727,-9 ; 1701,-9 1728.02,-36.02 ; 1707.99,-183.99 1714,-190 1720.01,-183.99 ; 1707.98,-36.02 1735,-9 ; 1709,-9 1736.02,-36.02 ; 1715.99,-183.99 1722,-190 1728.01,-183.99 ; 1717,-9 1744.02,-36.02 ; 1723.99,-183.99 1730,-190 1736.01,-183.99 ; 1725,-9 1752.02,-36.02 ; 1731.99,-183.99 1738,-190 1744.01,-183.99 ; 1733,-9 1760.02,-36.02 ; 1739.99,-183.99 1746,-190 1752.01,-183.99 ; 1740.25,-8.25 1768.02,-36.02 ; 1744.25,-4.25 1776.02,-36.02 ; 1747.99,-183.99 1754,-190 1760.01,-183.99 ; 1747.98,-36.02 1777.75,-6.25 ; 1755.99,-183.99 1762,-190 1768.01,-183.99 ; 1755.98,-36.02 1783,-9 ; 1763.99,-183.99 1770,-190 1776.01,-183.99 ; 1763.98,-36.02 1791,-9 ; 1771.99,-183.99 1778,-190 1784.01,-183.99 ; 1771.98,-36.02 1799,-9 ; 1779.99,-183.99 1786,-190 1792.01,-183.99 ; 1779.98,-36.02 1807,-9 ; 1780.5,-9 1839.5,-9 ; 1781,-9 1808.02,-36.02 ; 1787.99,-183.99 1794,-190 1800.01,-183.99 ; 1787.98,-36.02 1815,-9 ; 1789,-9 1816.02,-36.02 ; 1795.99,-183.99 1802,-190 1808.01,-183.99 ; 1795.98,-36.02 1823,-9 ; 1797,-9 1824.02,-36.02 ; 1803.99,-183.99 1810,-190 1816.01,-183.99 ; 1803.98,-36.02 1831,-9 ; 1805,-9 1832.02,-36.02 ; 1811.99,-183.99 1818,-190 1824.01,-183.99 ; 1811.98,-36.02 1839,-9 ; 1813,-9 1840.02,-36.02 ; 1819.99,-183.99 1826,-190 1832.01,-183.99 ; 1821,-9 1848.02,-36.02 ; 1827.99,-183.99 1834,-190 1840.01,-183.99 ; 1829,-9 1856.02,-36.02 ; 1835.99,-183.99 1842,-190 1848.01,-183.99 ; 1837,-9 1864.02,-36.02 ; 1842.25,-6.25 1872.02,-36.02 ; 1843.99,-183.99 1850,-190 1856.01,-183.99 ; 1843.98,-36.02 1875.75,-4.25 ; 1851.99,-183.99 1858,-190 1864.01,-183.99 ; 1851.98,-36.02 1879.75,-8.25 ; 1859.99,-183.99 1866,-190 1872.01,-183.99 ; 1859.98,-36.02 1887,-9 ; 1867.99,-183.99 1874,-190 1880.01,-183.99 ; 1867.98,-36.02 1895,-9 ; 1875.99,-183.99 1882,-190 1888.01,-183.99 ; 1875.98,-36.02 1903,-9 ; 1880.5,-9 1939.5,-9 ; 1883.99,-183.99 1890,-190 1896.01,-183.99 ; 1883.98,-36.02 1911,-9 ; 1885,-9 1912.02,-36.02 ; 1891.99,-183.99 1898,-190 1904.01,-183.99 ; 1891.98,-36.02 1919,-9 ; 1893,-9 1920.02,-36.02 ; 1899.99,-183.99 1906,-190 1912.01,-183.99 ; 1899.98,-36.02 1927,-9 ; 1901,-9 1928.02,-36.02 ; 1907.99,-183.99 1914,-190 1920.01,-183.99 ; 1907.98,-36.02 1935,-9 ; 1909,-9 1936.02,-36.02 ; 1915.99,-183.99 1922,-190 1928.01,-183.99 ; 1917,-9 1944.02,-36.02 ; 1923.99,-183.99 1930,-190 1936.01,-183.99 ; 1925,-9 1952.02,-36.02 ; 1931.99,-183.99 1938,-190 1944.01,-183.99 ; 1933,-9 1960.02,-36.02 ; 1939.99,-183.99 1946,-190 1952.01,-183.99 ; 1940.25,-8.25 1968.02,-36.02 ; 1944.25,-4.25 1976.02,-36.02 ; 1947.99,-183.99 1954,-190 1960.01,-183.99 ; 1947.98,-36.02 1977.75,-6.25 ; 1955.99,-183.99 1962,-190 1968.01,-183.99 ; 1955.98,-36.02 1983,-9 ; 1963.99,-183.99 1970,-190 1976.01,-183.99 ; 1963.98,-36.02 1991,-9 ; 1971.99,-183.99 1978,-190 1984.01,-183.99 ; 1971.98,-36.02 1999,-9 ; 1979.99,-183.99 1986,-190 1992.01,-183.99 ; 1979.98,-36.02 2007,-9 ; 1980.5,-9 2039.5,-9 ; 1981,-9 2008.02,-36.02 ; 1987.99,-183.99 1994,-190 2000.01,-183.99 ; 1987.98,-36.02 2015,-9 ; 1989,-9 2016.02,-36.02 ; 1995.99,-183.99 2002,-190 2008.01,-183.99 ; 1995.98,-36.02 2023,-9 ; 1997,-9 2024.02,-36.02 ; 2003.99,-183.99 2010,-190 2016.01,-183.99 ; 2003.98,-36.02 2031,-9 ; 2005,-9 2032.02,-36.02 ; 2011.99,-183.99 2018,-190 2024.01,-183.99 ; 2011.98,-36.02 2039,-9 ; 2013,-9 2040.02,-36.02 ; 2019.99,-183.99 2026,-190 2032.01,-183.99 ; 2019.98,-36.02 2051,-5 ; 2021,-9 2048.02,-36.02 ; 2027.99,-183.99 2034,-190 2040.01,-183.99 ; 2027.98,-36.02 2055,-9 ; 2029,-9 2056.02,-36.02 ; 2035.99,-183.99 2042,-190 2048.01,-183.99 ; 2035.98,-36.02 2063,-9 ; 2037,-9 2064.02,-36.02 ; 2042.25,-6.25 2072.02,-36.02 ; 2043.99,-183.99 2050,-190 2056.01,-183.99 ; 2043.98,-36.02 2071,-9 ; 2051,-9 2169,-9 ; 2051,-7 2053,-9 2080.02,-36.02 ; 2051.99,-183.99 2058,-190 2064.01,-183.99 ; 2051.98,-36.02 2079,-9 ; 2059.99,-183.99 2066,-190 2072.01,-183.99 ; 2059.98,-36.02 2087,-9 ; 2061,-9 2088.02,-36.02 ; 2067.99,-183.99 2074,-190 2080.01,-183.99 ; 2067.98,-36.02 2095,-9 ; 2069,-9 2096.02,-36.02 ; 2075.99,-183.99 2082,-190 2088.01,-183.99 ; 2075.98,-36.02 2103,-9 ; 2077,-9 2104.02,-36.02 ; 2083.99,-183.99 2090,-190 2096.01,-183.99 ; 2083.98,-36.02 2111,-9 ; 2085,-9 2112.02,-36.02 ; 2091.99,-183.99 2098,-190 2104.01,-183.99 ; 2091.98,-36.02 2119,-9 ; 2093,-9 2120.02,-36.02 ; 2099.99,-183.99 2106,-190 2112.01,-183.99 ; 2099.98,-36.02 2127,-9 ; 2101,-9 2128.02,-36.02 ; 2107.99,-183.99 2114,-190 2120.01,-183.99 ; 2107.98,-36.02 2135,-9 ; 2109,-9 2136.02,-36.02 ; 2115.99,-183.99 2122,-190 2128.01,-183.99 ; 2115.98,-36.02 2143,-9 ; 2117,-9 2144.02,-36.02 2153.68,-45.68 2298,-190 2394,-94 2490,-190 2586,-94 2682,-190 2713,-159 ; 2123.99,-183.99 2130,-190 2136.01,-183.99 ; 2123.98,-36.02 2151,-9 ; 2125,-9 2152.02,-36.02 2153.68,-37.68 2306,-190 2402,-94 2498,-190 2594,-94 2690,-190 2717,-163 ; 2131.99,-183.99 2138,-190 2144.01,-183.99 2153.68,-174.32 2278.5,-49.5 ; 2131.98,-36.02 2159,-9 ; 2133,-9 2314,-190 2410,-94 2506,-190 2602,-94 2698,-190 2721,-167 ; 2139.99,-183.99 2146,-190 2152.01,-183.99 2153.68,-182.32 2282.5,-53.5 ; 2139.98,-36.02 2167,-9 2169,-7 ; 2141,-9 2322,-190 2418,-94 2514,-190 2610,-94 2706,-190 2725,-171 ; 2147.99,-183.99 2154,-190 2286.5,-57.5 ; 2149,-9 2330,-190 2426,-94 2522,-190 2618,-94 2714,-190 2730,-174 ; 2153.68,-181.68 2162,-190 2290.5,-61.5 ; 2153.68,-173.68 2170,-190 2294.5,-65.5 ; 2153.68,-166.32 2274.5,-45.5 ; 2153.68,-165.68 2178,-190 2298.5,-69.5 ; 2153.68,-158.32 2270.5,-41.5 ; 2153.68,-157.68 2186,-190 2302.5,-73.5 ; 2153.68,-150.32 2266.5,-37.5 ; 2153.68,-149.68 2194,-190 2306.5,-77.5 ; 2153.68,-142.32 2262.5,-33.5 ; 2153.68,-141.68 2202,-190 2310.5,-81.5 ; 2153.68,-134.32 2258.5,-29.5 ; 2153.68,-133.68 2210,-190 2314.5,-85.5 ; 2153.68,-126.32 2254.5,-25.5 ; 2153.68,-125.68 2218,-190 2318.5,-89.5 ; 2153.68,-118.32 2251,-21 ; 2153.68,-117.68 2226,-190 2322.5,-93.5 ; 2153.68,-110.32 2251,-13 ; 2153.68,-109.68 2234,-190 2330,-94 2426,-190 2522,-94 2618,-190 2686,-122 2657.5,-93.5 ; 2153.68,-102.32 2251,-5 ; 2153.68,-101.68 2242,-190 2338,-94 2434,-190 2530,-94 2626,-190 2686,-130 ; 2153.68,-93.68 2250,-190 2346,-94 2442,-190 2538,-94 2634,-190 2689,-135 ; 2153.68,-85.68 2258,-190 2354,-94 2450,-190 2546,-94 2642,-190 2693,-139 ; 2153.68,-77.68 2266,-190 2362,-94 2458,-190 2554,-94 2650,-190 2697,-143 ; 2153.68,-69.68 2274,-190 2370,-94 2466,-190 2562,-94 2658,-190 2701,-147 ; 2153.68,-61.68 2282,-190 2378,-94 2474,-190 2570,-94 2666,-190 2705,-151 ; 2153.68,-53.68 2290,-190 2386,-94 2482,-190 2578,-94 2674,-190 2709,-155 ; 2157,-9 2338,-190 2434,-94 2530,-190 2626,-94 2722,-190 2738,-174 2754,-190 2770,-174 2786,-190 2802,-174 2818,-190 2860,-148 ; 2165,-9 2346,-190 2442,-94 2538,-190 2634,-94 2730,-190 2746,-174 2762,-190 2778,-174 2794,-190 2810,-174 ; 2169,-5 2354,-190 2450,-94 2546,-190 2642,-94 2738,-190 2754,-174 2770,-190 2786,-174 2802,-190 2860,-132 ; 2362,-190 2458,-94 2554,-190 2650,-94 2686,-130 ; 2370,-190 2466,-94 2562,-190 2686,-66 2685.5,-65.5 ; 2378,-190 2474,-94 2570,-190 2686,-74 2681.5,-69.5 ; 2386,-190 2482,-94 2578,-190 2686,-82 2677.5,-73.5 ; 2394,-190 2490,-94 2586,-190 2686,-90 2673.5,-77.5 ; 2402,-190 2498,-94 2594,-190 2686,-98 2669.5,-81.5 ; 2410,-190 2506,-94 2602,-190 2686,-106 2665.5,-85.5 ; 2418,-190 2514,-94 2610,-190 2686,-114 2661.5,-89.5 ; 2745,-6 2812,-6 2854,-48 2854,-132 2812,-174 2728,-174 2686,-132 2686,-65 2674,-77 ; 2745.5,-5.5 2746,-6 ; 2810,-6 2854,-50 ; 2815,-171 2834,-190 2860,-164 ; 2819,-167 2842,-190 2860,-172 ; 2823,-163 2850,-190 2860,-180 ; 2827,-159 2858,-190 2860,-188 ; 2831,-155 2860,-184 ; 2835,-151 2860,-176 ; 2839,-147 2860,-168 ; 2839,-33 2860,-12 ; 2843,-143 2860,-160 ; 2843,-37 2860,-20 ; 2847,-139 2860,-152 ; 2847,-41 2860,-28 ; 2851,-135 2860,-144 ; 2851,-45 2860,-36 ; 2860,-156 2826,-190 2810,-174 ; 2860,-140 2810,-190 2794,-174 2778,-190 2762,-174 2746,-190 2730,-174 ; 2860,-136 2854,-130 ; 2860,-128 2854,-122 2860,-116 ; 2860,-124 2854,-130 ; 2860,-120 2854,-114 2860,-108 ; 2860,-112 2854,-106 2860,-100 ; 2860,-104 2854,-98 2860,-92 ; 2860,-96 2854,-90 2860,-84 ; 2860,-88 2854,-82 2860,-76 ; 2860,-80 2854,-74 2860,-68 ; 2860,-72 2854,-66 2860,-60 ; 2860,-64 2854,-58 2860,-52 ; 2860,-56 2854,-50 ; 2860,-44 2854,-50 ; -90,-186 -50,-146 -90,-186 ; -64,-132 -22,-174 ; -64,-132 -22,-174 ; -64,-132 -64,-48 ; -64,-48 -22,-6 ; -64,-48 -22,-6 ; -22,-174 62,-174 104,-132 ; -22,-6 62,-6 104,-48 104,-132 ; 193,-24 227,-24 ; 193,-24 227,-24 ; 193,-24 176,-7 193,-24 ; 227,-24 1043,-24 ; 1043,-24 1077,-24 ; 1043,-24 1077,-24 ; 1077,-24 1094,-7 1077,-24 ; 2268,-39 2306,-77 ; 2268,-39 2251,-22 2268,-39 ; 2306,-77 2323,-94 ; 2306,-77 2323,-94 ; 2323,-94 2357,-94 ; 2323,-94 2357,-94 ; 2357,-94 2623,-94 ; 2623,-94 2657,-94 ; 2623,-94 2657,-94 ; 2657,-94 2674,-77 ; 2657,-94 2674,-77 ; 2686,-130 2730,-174 ; 2810,-174 2854,-130 ; 253,-169 253,-71.01 560.92,-71.01 560.92,-169 253,-169 ; 1106,-183.99 1106,-36.02 2153.68,-36.02 2153.68,-183.99 1106,-183.99
  Top Layer w10: -60,-90 20,-90 ; 20,-170 20,-90 ; 20,-10 20,-90 ; 100,-90 20,-90 ; 2690,-90 2770,-90 ; 2770,-170 2770,-90 ; 2770,-10 2770,-90 ; 2850,-90 2770,-90
  Bottom Layer w8: -90,-190 2860,-190 ; -90,-66 -64,-92 ; -90,-58 -64,-84 ; -90,-50 -64,-76 ; -90,-42 -64,-68 ; -90,-34 -64,-60 ; -90,-26 -64,-52 ; -90,-18 -62,-46 ; -90,-10 -58,-42 ; -64,-128 -90,-154 -54,-190 -30,-166 ; -64,-124 -90,-98 -64,-72 ; -64,-120 -90,-146 -46,-190 -26,-170 ; -64,-116 -90,-90 -64,-64 ; -64,-112 -90,-138 -38,-190 -22,-174 ; -64,-108 -90,-82 -64,-56 ; -64,-104 -90,-130 -30,-190 -14,-174 2,-190 18,-174 34,-190 50,-174 66,-190 ; -64,-100 -90,-74 -64,-48 ; -64,-96 -90,-122 -22,-190 -6,-174 10,-190 26,-174 42,-190 58,-174 74,-190 ; -64,-88 -90,-114 -14,-190 2,-174 18,-190 34,-174 50,-190 ; -64,-80 -90,-106 -64,-132 ; -62,-134 -90,-162 -62,-190 -34,-162 ; -58,-138 -90,-170 -70,-190 -38,-158 ; -54,-142 -90,-178 -78,-190 -42,-154 ; -46,-150 -86,-190 -90,-186 ; 58,-190 42,-174 26,-190 10,-174 -6,-190 -22,-174 ; 64,-172 82,-190 ; 68,-168 90,-190 201.11,-78.89 208.99,-71.01 ; 72,-164 98,-190 201.11,-86.89 ; 76,-160 106,-190 201.11,-94.89 ; 80,-156 114,-190 201.11,-102.89 ; 84,-152 122,-190 201.11,-110.89 ; 88,-148 130,-190 201.11,-118.89 ; 92,-144 138,-190 201.11,-126.89 ; 96,-140 146,-190 201.11,-134.89 ; 100,-136 154,-190 201.11,-142.89 ; 104,-124 170,-190 201.11,-158.89 ; 104,-116 178,-190 201.11,-166.89 ; 104,-108 186,-190 207,-169 ; 104,-100 194,-190 215,-169 ; 104,-92 202,-190 223,-169 ; 104,-84 210,-190 231,-169 ; 104,-76 218,-190 239,-169 ; 104,-68 201.11,-165.11 205,-169 226,-190 247,-169 ; 104,-60 201.11,-157.11 213,-169 234,-190 255,-169 ; 104,-52 201.11,-149.11 ; 201.11,-150.89 162,-190 104,-132 ; 221,-169 242,-190 263,-169 ; 229,-169 250,-190 271,-169 ; 237,-169 258,-190 279,-169 ; 245,-169 266,-190 287,-169 ; 253,-169 274,-190 295,-169 ; 261,-169 282,-190 303,-169 ; 269,-169 290,-190 311,-169 ; 277,-169 298,-190 319,-169 ; 285,-169 306,-190 327,-169 ; 293,-169 314,-190 335,-169 ; 301,-169 322,-190 343,-169 ; 309,-169 330,-190 351,-169 ; 317,-169 338,-190 359,-169 ; 325,-169 346,-190 367,-169 ; 333,-169 354,-190 375,-169 ; 341,-169 362,-190 383,-169 ; 349,-169 370,-190 391,-169 ; 357,-169 378,-190 399,-169 ; 365,-169 386,-190 407,-169 ; 373,-169 394,-190 415,-169 ; 381,-169 402,-190 423,-169 ; 389,-169 410,-190 431,-169 ; 397,-169 418,-190 439,-169 ; 405,-169 426,-190 447,-169 ; 413,-169 434,-190 455,-169 ; 421,-169 442,-190 463,-169 ; 429,-169 450,-190 471,-169 ; 437,-169 458,-190 479,-169 ; 445,-169 466,-190 487,-169 ; 453,-169 474,-190 495,-169 ; 461,-169 482,-190 503,-169 ; 469,-169 490,-190 511,-169 ; 477,-169 498,-190 519,-169 ; 485,-169 506,-190 527,-169 ; 493,-169 514,-190 535,-169 ; 501,-169 522,-190 543,-169 ; 509,-169 530,-190 551,-169 ; 517,-169 538,-190 559,-169 ; 525,-169 546,-190 567,-169 ; 533,-169 554,-190 575,-169 589,-155 ; 541,-169 562,-190 583,-169 589,-163 ; 549,-169 570,-190 ; 557,-169 578,-190 ; 565,-169 586,-190 ; 573,-169 594,-190 ; 579.01,-71.01 589,-81 698,-190 ; 581,-169 602,-190 ; 587.01,-71.01 589,-73 706,-190 ; 589,-161 618,-190 ; 589,-153 626,-190 ; 589,-145 634,-190 ; 589,-137 642,-190 ; 589,-129 650,-190 ; 589,-121 658,-190 ; 589,-113 666,-190 ; 589,-105 674,-190 ; 589,-97 682,-190 ; 589,-89 690,-190 ; 610,-190 589,-169 ; 1090,-190 1275.75,-4.25 ; 1098,-190 1279.75,-8.25 ; 1106,-190 1287,-9 ; 1114,-190 1295,-9 ; 1122,-190 1303,-9 ; 1130,-190 1311,-9 ; 1138,-190 1319,-9 ; 1146,-190 1327,-9 ; 1154,-190 1335,-9 ; 1194,-190 1377.75,-6.25 ; 1202,-190 1383,-9 ; 1210,-190 1391,-9 ; 1218,-190 1399,-9 ; 1226,-190 1407,-9 ; 1234,-190 1415,-9 ; 1242,-190 1423,-9 ; 1250,-190 1431,-9 ; 1258,-190 1439,-9 ; 1280.5,-9 1339.5,-9 ; 1285,-9 1466,-190 ; 1290,-190 1475.75,-4.25 ; 1293,-9 1474,-190 ; 1298,-190 1479.75,-8.25 ; 1301,-9 1482,-190 ; 1306,-190 1487,-9 ; 1309,-9 1490,-190 1675.75,-4.25 ; 1314,-190 1495,-9 ; 1317,-9 1498,-190 1679.75,-8.25 ; 1322,-190 1503,-9 ; 1325,-9 1506,-190 1687,-9 ; 1330,-190 1511,-9 ; 1333,-9 1514,-190 1695,-9 ; 1338,-190 1519,-9 ; 1340.25,-8.25 1522,-190 1703,-9 ; 1344.25,-4.25 1530,-190 1711,-9 ; 1346,-190 1527,-9 ; 1354,-190 1535,-9 ; 1380.5,-9 1439.5,-9 ; 1381,-9 1562,-190 ; 1389,-9 1570,-190 ; 1394,-190 1577.75,-6.25 ; 1397,-9 1578,-190 ; 1402,-190 1583,-9 ; 1405,-9 1586,-190 ; 1410,-190 1591,-9 ; 1413,-9 1594,-190 1777.75,-6.25 ; 1418,-190 1599,-9 ; 1421,-9 1602,-190 1783,-9 ; 1426,-190 1607,-9 ; 1429,-9 1610,-190 1791,-9 ; 1434,-190 1615,-9 ; 1437,-9 1618,-190 1799,-9 ; 1442,-190 1623,-9 ; 1442.25,-6.25 1626,-190 1807,-9 ; 1450,-190 1631,-9 ; 1458,-190 1639,-9 ; 1480.5,-9 1539.5,-9 ; 1485,-9 1666,-190 ; 1493,-9 1674,-190 ; 1501,-9 1682,-190 ; 1509,-9 1690,-190 1875.75,-4.25 ; 1517,-9 1698,-190 1879.75,-8.25 ; 1525,-9 1706,-190 1887,-9 ; 1533,-9 1714,-190 1895,-9 ; 1538,-190 1719,-9 ; 1540.25,-8.25 1722,-190 1903,-9 ; 1544.25,-4.25 1730,-190 1911,-9 ; 1546,-190 1727,-9 ; 1554,-190 1735,-9 ; 1580.5,-9 1639.5,-9 ; 1581,-9 1762,-190 ; 1589,-9 1770,-190 ; 1597,-9 1778,-190 ; 1605,-9 1786,-190 ; 1613,-9 1794,-190 1977.75,-6.25 ; 1621,-9 1802,-190 1983,-9 ; 1629,-9 1810,-190 1991,-9 ; 1634,-190 1815,-9 ; 1637,-9 1818,-190 1999,-9 ; 1642,-190 1823,-9 ; 1642.25,-6.25 1826,-190 2007,-9 ; 1650,-190 1831,-9 ; 1658,-190 1839,-9 ; 1680.5,-9 1739.5,-9 ; 1685,-9 1866,-190 2051,-5 ; 1693,-9 1874,-190 2055,-9 ; 1701,-9 1882,-190 2063,-9 ; 1709,-9 1890,-190 2071,-9 ; 1717,-9 1898,-190 2079,-9 ; 1725,-9 1906,-190 2087,-9 ; 1733,-9 1914,-190 2095,-9 ; 1738,-190 1919,-9 ; 1740.25,-8.25 1922,-190 2103,-9 ; 1744.25,-4.25 1930,-190 2111,-9 ; 1746,-190 1927,-9 ; 1754,-190 1935,-9 ; 1780.5,-9 1839.5,-9 ; 1781,-9 1962,-190 2143,-9 ; 1789,-9 1970,-190 2151,-9 ; 1797,-9 1978,-190 2159,-9 ; 1805,-9 1986,-190 2167,-9 2169,-7 ; 1813,-9 1994,-190 ; 1821,-9 2002,-190 ; 1829,-9 2010,-190 ; 1834,-190 2015,-9 ; 1837,-9 2018,-190 ; 1842,-190 2023,-9 ; 1842.25,-6.25 2026,-190 ; 1850,-190 2031,-9 ; 1858,-190 2039,-9 ; 1880.5,-9 1939.5,-9 ; 1885,-9 2066,-190 ; 1893,-9 2074,-190 ; 1901,-9 2082,-190 ; 1909,-9 2090,-190 ; 1917,-9 2098,-190 ; 1925,-9 2106,-190 ; 1933,-9 2114,-190 ; 1938,-190 2119,-9 ; 1940.25,-8.25 2122,-190 ; 1944.25,-4.25 2130,-190 ; 1946,-190 2127,-9 ; 1954,-190 2135,-9 ; 1980.5,-9 2039.5,-9 ; 1981,-9 2162,-190 ; 1989,-9 2170,-190 ; 1997,-9 2178,-190 ; 2005,-9 2186,-190 ; 2013,-9 2194,-190 2373.5,-10.5 ; 2021,-9 2202,-190 2373.5,-18.5 ; 2029,-9 2210,-190 2373.5,-26.5 ; 2037,-9 2218,-190 2376.62,-31.38 ; 2042.25,-6.25 2226,-190 2380.62,-35.38 ; 2051,-9 2169,-9 ; 2051,-7 2053,-9 2234,-190 2384.62,-39.38 ; 2061,-9 2242,-190 2388.62,-43.38 ; 2069,-9 2250,-190 2392.62,-47.38 ; 2077,-9 2258,-190 2396.62,-51.38 ; 2085,-9 2266,-190 2400.62,-55.38 ; 2093,-9 2274,-190 2407.5,-56.5 ; 2101,-9 2282,-190 2415.5,-56.5 ; 2109,-9 2290,-190 2423.5,-56.5 ; 2117,-9 2298,-190 2431.5,-56.5 ; 2125,-9 2306,-190 2439.5,-56.5 ; 2133,-9 2314,-190 2447.5,-56.5 ; 2141,-9 2322,-190 2455.5,-56.5 2486.5,-25.5 ; 2149,-9 2330,-190 ; 2157,-9 2338,-190 ; 2165,-9 2346,-190 ; 2169,-5 2354,-190 ; 2373.5,-28.25 2401.75,-56.5 2458.25,-56.5 2486.5,-28.25 ; 2373.5,-25.5 2404.5,-56.5 2538,-190 ; 2412.5,-56.5 2546,-190 2686,-50 2730,-6 ; 2420.5,-56.5 2554,-190 2686,-58 ; 2428.5,-56.5 2562,-190 2686,-66 ; 2436.5,-56.5 2570,-190 2686,-74 ; 2444.5,-56.5 2578,-190 2686,-82 ; 2452.5,-56.5 2586,-190 2686,-90 ; 2459.38,-55.38 2594,-190 2686,-98 ; 2463.38,-51.38 2602,-190 2686,-106 ; 2467.38,-47.38 2610,-190 2686,-114 ; 2471.38,-43.38 2618,-190 2686,-122 ; 2475.38,-39.38 2626,-190 2686,-130 2730,-174 ; 2479.38,-35.38 2634,-190 2689,-135 ; 2483.38,-31.38 2642,-190 2693,-139 ; 2486.5,-26.5 2650,-190 2697,-143 ; 2486.5,-18.5 2658,-190 2701,-147 ; 2486.5,-10.5 2666,-190 2705,-151 ; 2674,-190 2709,-155 ; 2682,-190 2713,-159 ; 2690,-190 2717,-163 ; 2698,-190 2721,-167 ; 2706,-190 2725,-171 ; 2714,-190 2730,-174 ; 2722,-190 2738,-174 2754,-190 2770,-174 2786,-190 2802,-174 2818,-190 2860,-148 ; 2730,-190 2746,-174 2762,-190 2778,-174 2794,-190 2810,-174 ; 2738,-190 2754,-174 2770,-190 2786,-174 2802,-190 2860,-132 ; 2810,-6 2854,-50 ; 2815,-171 2834,-190 2860,-164 ; 2819,-167 2842,-190 2860,-172 ; 2823,-163 2850,-190 2860,-180 ; 2827,-159 2858,-190 2860,-188 ; 2831,-155 2860,-184 ; 2835,-151 2860,-176 ; 2839,-147 2860,-168 ; 2839,-33 2860,-12 ; 2843,-143 2860,-160 ; 2843,-37 2860,-20 ; 2847,-139 2860,-152 ; 2847,-41 2860,-28 ; 2851,-135 2860,-144 ; 2851,-45 2860,-36 ; 2860,-156 2826,-190 2810,-174 ; 2860,-140 2810,-190 2794,-174 2778,-190 2762,-174 2746,-190 2730,-174 ; 2860,-136 2854,-130 ; 2860,-128 2854,-122 2860,-116 ; 2860,-124 2854,-130 ; 2860,-120 2854,-114 2860,-108 ; 2860,-112 2854,-106 2860,-100 ; 2860,-104 2854,-98 2860,-92 ; 2860,-96 2854,-90 2860,-84 ; 2860,-88 2854,-82 2860,-76 ; 2860,-80 2854,-74 2860,-68 ; 2860,-72 2854,-66 2860,-60 ; 2860,-64 2854,-58 2860,-52 ; 2860,-56 2854,-50 ; 2860,-44 2854,-50 ; -90,-186 -50,-146 -90,-186 ; -64,-132 -22,-174 ; -64,-132 -22,-174 ; -64,-132 -64,-48 ; -64,-48 -22,-6 ; -64,-48 -22,-6 ; -22,-174 62,-174 104,-132 ; -22,-6 62,-6 104,-48 104,-132 ; 589,-169 201.11,-169 201.11,-71.01 589,-71.01 589,-169 ; 2810,-174 2854,-130 ; 2686,-132 2728,-174 2812,-174 2854,-132 2854,-48 2812,-6 2728,-6 2686,-48 2686,-132
  Bottom Layer w10: -60,-90 20,-90 ; 20,-170 20,-90 ; 20,-10 20,-90 ; 100,-90 20,-90 ; 2690,-90 2770,-90 ; 2770,-170 2770,-90 ; 2770,-10 2770,-90 ; 2850,-90 2770,-90

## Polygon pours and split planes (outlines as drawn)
GND on Top Layer (hatched 45Degree grid 0 track 8): -90,1850 2840,1850 2840,3740 -90,3740

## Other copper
Top Layer:
  rectangle net VDD: 210,3450 645,3640
  rectangle net "Net24V OUT_1": 220,2070 670,2710
  rectangle net VDD: 210,3330 560,3450
  rectangle net Net7905_2: 330,2860 500,3010
  rectangle net NetJP5_1: 2400,3230 2676,3410
  text "Weller" at 2410,3648 h40
  text "24V 50W" at 2370,3540 h40
  text "- +" at -55,2700 h60 r270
